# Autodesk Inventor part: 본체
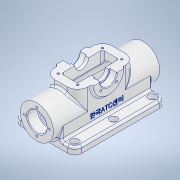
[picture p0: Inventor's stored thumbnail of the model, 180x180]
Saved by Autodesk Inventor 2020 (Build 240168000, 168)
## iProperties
Created: 2024-06
Part Number: 본체
Material: 알루미늄 6061
Document SubType Name: Modeling
Designer: oem
Mass: 550.805 g
Surface Area: 613.924 cm^2
Volume: 204.002 cm^3
Density: 2.7 g/cm^3
Appearance: 알루미늄 - 평지
Author: oem
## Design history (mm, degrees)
sketch "스케치1"
  geometry: C1 r 24 at (0, 0); 1 further point
  constraints: 1 centre point, 1 coincident
  dimensions: "d0" = 48 diameter of C1
extrude "돌출1" new body sketch "스케치1" stored distance "d1" = 154; taper "d2" = 0 deg
node "작업 평면1"
sketch "스케치2"
  geometry: L1 (-24, -77)-(-24, 77) reference; L2 (24, 42)-(-24, 42); L3 (-24, 42)-(-24, -42); L4 (-24, -42)-(24, -42); L5 (24, -42)-(24, 42); L6 (24, 42)-(-24, -42); L7 (-24, 42)-(24, -42); 2 further points
  constraints: 12 end point, 2 midpoint, 2 parallel, 1 horizontal, 1 perpendicular, 1 point on line
  dimensions: "d4" = 84 distance of L3.end L2.end
extrude "돌출2" join sketch "스케치2" stored distance "d5" = 154; taper "d6" = 0 deg
fillet "모깎기1" dims "d8" = 15
sketch "스케치3"
  geometry: L1 (-24, 0)-(-24, -18); L2 (-24, -18)-(-44, -18); L3 (-44, -18)-(-44, -28); L4 (-44, -28)-(44, -28); L5 (44, -28)-(44, -18); L6 (44, -18)-(24, -18); L7 (24, -18)-(24, 0); A1 r 24 centre (0, 0) between (-24, 0) and (24, 0) reference; 2 further points
  constraints: 14 end point, 4 perpendicular, 2 point on circle, 2 point on line, 2 tangent, 1 midpoint, 1 parallel, 1 vertical, 1 vertical alignment
  dimensions: "d9" = 10 distance of L2.end L3.end; "d10" = 88 distance of L3.end L4.end; "d11" = 28 distance of point (0, 0) point (0, -28)
extrude "돌출3" join sketch "스케치3" stored distance "d12" = 132; taper "d13" = 0 deg
sketch "스케치4"
  geometry: C1 r 24 at (0, 0) reference; C2 r 14 at (0, 0)
  constraints: 1 centre point, 1 coincident
  dimensions: "d14" = 28 diameter of C2
extrude "돌출4" cut sketch "스케치4" distance "d15" = 15; taper "d16" = 0 deg
sketch "스케치5"
  geometry: C1 r 24 at (0, 0) reference; C2 r 14 at (0, 0)
  constraints: 1 centre point, 1 coincident
  dimensions: "d17" = 28 diameter of C2
extrude "돌출5" cut sketch "스케치5" distance "d18" = 15; taper "d19" = 0 deg
sketch "스케치6"
  geometry: C1 r 14 at (0, 0) reference; C2 r 11 at (0, 0)
  constraints: 1 centre point, 1 coincident
  dimensions: "d21" = 22 diameter of C2
extrude "돌출6" cut sketch "스케치6" extent not by distance; stored distance "d22" = 15; taper "d23" = 0 deg
sketch "스케치7"
  geometry: L1 (-12, -30)-(12, -30); L2 (12, -30)-(12, 30); L3 (12, 30)-(-12, 30); L4 (-12, 30)-(-12, -30); L5 (-12, -30)-(12, 30); L6 (12, -30)-(-12, 30); 1 further point
  constraints: 12 end point, 2 midpoint, 2 parallel, 1 horizontal, 1 perpendicular
  dimensions: "d24" = 24 distance of L3.end L2.end; "d25" = 60 distance of L2.end L1.end
extrude "돌출7" cut sketch "스케치7" extent not by distance; stored distance "d26" = 0; taper "d27" = 0 deg
fillet "모깎기2" dims "d28" = 3
sketch "스케치8"
  geometry: L1 (-14, 32)-(14, 32); L2 (-14, -32)-(-14, 32); 4 further points
  constraints: 4 end point, 3 horizontal alignment, 3 vertical alignment, 2 midpoint, 1 horizontal, 1 perpendicular
  dimensions: "d29" = 64 distance of L1.start L2.start; "d30" = 28 distance of L1.end L1.start
hole "구멍1" sketch "스케치8" at (-14, 32), (14, 32), (14, -32), (-14, -32) diameter "d31" = 3.242; stored, may be unused: countersink angle "d35" = 90 deg, drill point angle "d37" = 118 deg; dims "d32" = 8, "d33" = 8, "d34" = 2, "d36" = 10
sketch "스케치9"
  geometry: L1 (0, 0)-(54, 0) reference; L2 (0, 0)-(54, 0) reference; A1 r 22 centre (27, 0) between (5, 0) and (49, 0); 3 further points
  constraints: 2 point on circle, 2 point on line, 1 centre point, 1 midpoint
  dimensions: "d38" = 44 diameter of A1
extrude "돌출8" join sketch "스케치9" distance "d39" = 3; taper "d40" = 0 deg
sketch "스케치10"
  geometry: L1 (49, 0)-(5, 0) reference; A1 r 22 centre (27, 0) between (5, 0) and (49, 0) reference; A2 r 12 centre (27, 0) between (15, 0) and (39, 0); 1 further point
  constraints: 2 point on circle, 2 point on line, 1 centre point, 1 coincident
  dimensions: "d41" = 24 diameter of A2
extrude "돌출9" cut sketch "스케치10" distance "d42" = 10; taper "d43" = 0 deg
sketch "스케치11"
  geometry: L1 (0, 0)-(54, 0) reference; L2 (39, 0)-(15, 0) reference; A1 r 22 centre (27, 0) between (5, 0) and (49, 0); 1 further point
  constraints: 2 point on circle, 2 point on line, 1 centre point, 1 midpoint
  dimensions: "d44" = 44 diameter of A1
extrude "돌출10" join sketch "스케치11" distance "d45" = 3; taper "d46" = 0 deg
sketch "스케치12"
  geometry: L1 (49, 0)-(5, 0) reference; A1 r 22 centre (27, 0) between (5, 0) and (49, 0) reference; A2 r 12 centre (27, 0) between (15, 0) and (39, 0); 1 further point
  constraints: 2 point on circle, 2 point on line, 1 centre point, 1 coincident
  dimensions: "d47" = 24 diameter of A2
extrude "돌출11" cut sketch "스케치12" distance "d48" = 10; taper "d49" = 0 deg
sketch "스케치13"
  geometry: L1 (15, 0)-(39, 0) reference; A1 r 12 centre (27, 0) between (15, 0) and (39, 0) reference; A2 r 10 centre (27, 0) between (17, 0) and (37, 0); 1 further point
  constraints: 2 point on circle, 2 point on line, 1 centre point, 1 coincident
  dimensions: "d50" = 20 diameter of A2
extrude "돌출12" cut sketch "스케치13" extent not by distance; stored distance "d51" = 10; taper "d52" = 0 deg
sketch "스케치14"
  geometry: L1 (44, -28)-(-44, -28) reference; L2 (-18, -28)-(-18, 0); L3 (18, -28)-(18, 0); A1 r 18 centre (0, 0) between (18, 0) and (-18, 0); 2 further points
  constraints: 4 end point, 3 point on circle, 2 point on line, 2 tangent, 2 vertical, 1 centre point, 1 vertical alignment
  dimensions: "d53" = 18 radius of A1; "d54" = 28 distance of L3.start L3.end
extrude "돌출13" cut sketch "스케치14" stored distance "d55" = 120; taper "d56" = 0 deg
sketch "스케치15"
  geometry: C1 r 14 at (0, 0) reference; 1 further point
  constraints: 1 vertical alignment
  dimensions: "d57" = 18 distance of C1.centre point (0, 18)
hole "구멍2" sketch "스케치15" at (0, 18) diameter "d58" = 3.242; stored, may be unused: countersink angle "d62" = 90 deg, drill point angle "d64" = 118 deg; dims "d59" = 8, "d60" = 8, "d61" = 2, "d63" = 10
sketch "스케치16"
  geometry: L1 (20, 132)-(20, 0) reference; L2 (-68, 0)-(-68, 132) reference; L3 (-48, 0)-(-68, 0) reference; 7 further points
  constraints: 3 horizontal alignment, 3 vertical alignment
  dimensions: "d69" = 68 distance of point (10, 122) point (-58, 122); "d71" = 10 distance from line of L2 point (-58, 122); "d72" = 10 distance from line of L2 point (-58, 10); "d73" = 10 distance from line of L1 point (10, 122); "d74" = 112 distance of point (-58, 122) point (-58, 10); "d75" = 10 distance from line of point (-58, 10) L3
hole "구멍3" sketch "스케치16" at (10, 122), (10, 66), (10, 10), (-58, 10), (-58, 66), (-58, 122) diameter "d76" = 6.6; stored, may be unused: countersink angle "d80" = 90 deg, drill point angle "d82" = 118 deg; dims "d77" = 8, "d78" = 11, "d79" = 6.6, "d81" = 10
sketch "스케치17"
  geometry: L1 (27, 0)-(15.686, -11.314); L2 (27, 0)-(38.314, -11.314); L3 (27, 0)-(27, -31); A1 r 22 centre (27, 0) between (5, 0) and (49, 0) reference; A2 r 10 centre (27, 0) between (17, 0) and (37, 0) reference
  constraints: 6 end point, 1 perpendicular, 1 vertical
  dimensions: "d84" = 45 deg angle of L3 L1; "d85" = 16 distance of L1.start L1.end; "d86" = 45 deg angle of L3 L2
hole "구멍4" sketch "스케치17" at (15.686, -11.314), (38.314, -11.314) diameter "d87" = 3.242; stored, may be unused: countersink angle "d91" = 90 deg, drill point angle "d93" = 118 deg; dims "d88" = 8, "d89" = 11, "d90" = 6.6, "d92" = 10
sketch "스케치18"
  geometry: L1 (93, -28)-(-39, -28) reference; 2 further points
  constraints: 1 vertical alignment, 1 other
  dimensions: "d94" = 20 distance from line of L1 point (27, -8)
feature "엠보싱1" sketch "스케치18" dims "d0" = 48, "d95" = 0.5, "d96" = 0
fillet "모깎기3" dims "d97" = 10
fillet "모깎기4" dims "d98" = 3
fillet "모깎기5" dims "d99" = 3
fillet "모깎기6" dims "d100" = 3
chamfer "모따기1" distance "d101" = 1; stored, may be unused: second distance "d102" = 2, angle "d103" = 45 deg
fillet "모깎기7" dims "d104" = 3
fillet "모깎기8" dims "d105" = 3
fillet "모깎기9" dims "d106" = 0.3
fillet "모깎기10" dims "d107" = 3
fillet "모깎기11" dims "d108" = 3
fillet "모깎기12" dims "d109" = 3
fillet "모깎기13" dims "d110" = 3
node "솔리드1"
pattern_circular "원형 패턴1" dims angle "d66" = 360 deg
mirror "미러1"
mirror "미러2"
feature "A9D066F2-1C7D-4E18-AEED-F7BC21143FA4" dims "d76" = 6.6, "d77" = 8, "d78" = 11, "d79" = 6.6, "d80" = 90 deg, "d81" = 10, "d82" = 118 deg
other parameters: "d3" = 31
